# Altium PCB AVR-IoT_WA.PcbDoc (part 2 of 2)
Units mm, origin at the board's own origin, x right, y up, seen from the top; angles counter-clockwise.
Board outline 63.5 x 25.4 mm, 4 copper layers (Top-Layer, Ground Plane, Power Plane, Bottom Layer), stack 1.594 mm thick; 81 components, 91 nets, 345 pads, 206 vias.
Unrouted connection lines stored in the file: 10.
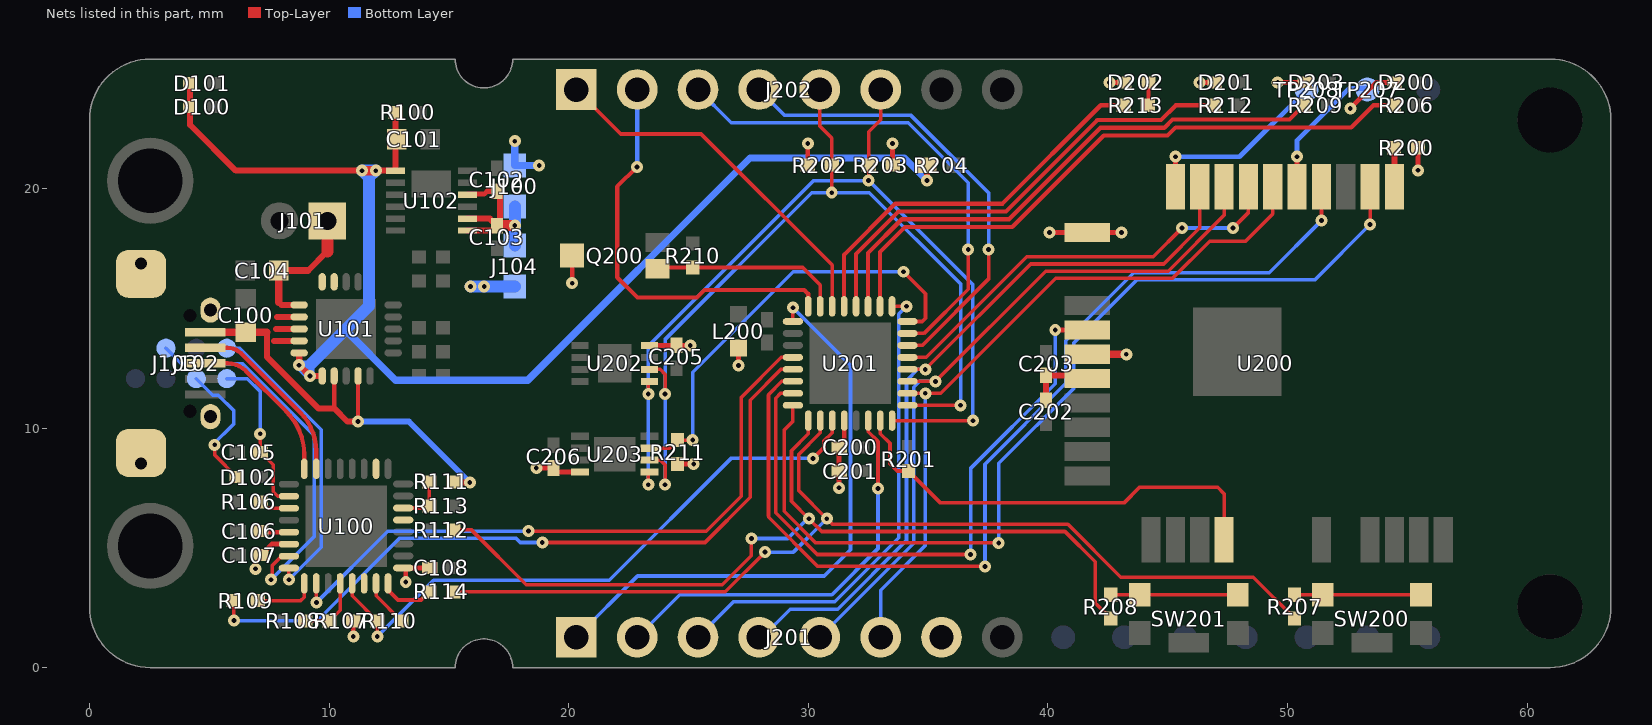
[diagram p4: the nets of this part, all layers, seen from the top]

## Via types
v1: diameter 0.5, hole 0.2, Top-Layer to Bottom Layer, 197 vias
v2: diameter 0.6, hole 0.3, Top-Layer to Bottom Layer, 9 vias

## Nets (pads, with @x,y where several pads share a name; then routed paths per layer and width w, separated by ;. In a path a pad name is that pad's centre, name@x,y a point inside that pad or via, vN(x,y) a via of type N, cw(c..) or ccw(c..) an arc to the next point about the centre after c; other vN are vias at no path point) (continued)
PA0_MBUS_RST: J201.2 U201.30 | length 17.1
  Top-Layer w0.15: U201.30@32.504,10.313 32.504,9.842 32.91,9.436 v1(32.91,7.484)
  Bottom Layer w0.15: J201.2@22.86,1.27 24.64,3.05 30.987,3.05 32.91,4.972 v1(32.91,7.484)
PA1_WINC_RST: R201.1 U200.4 U201.31 | length 18.9
  Top-Layer w0.15: U201.31@33.004,10.313 33.004,9.766 33.41,9.361 33.41,8.515 33.716,8.209 R201.1@34.185,8.209 35.519,6.875 43.177,6.875 43.827,7.525 47.086,7.525 47.356,7.255 U200.4@47.356,5.334
PA2_I2C_SDA: J202.6 R203.1 U201.32 U202.5 U203.1 | length 38.1
  Top-Layer w0.15: v1(23.323,7.639) 23.323,8.112 U203.1@23.373,8.162 ; v1(23.323,11.427) 23.323,11.9 U202.5@23.373,11.95 ; v1(32.52,20.331) R203.1@32.52,20.975 32.52,22.37 33.02,22.87 J202.6@33.02,24.13 ; U201.32@33.5,10.31 v1(36.872,10.31)
  Bottom Layer w0.15: v1(23.323,7.639) v1(23.323,11.427) 23.323,13.423 30.231,20.331 v1(32.52,20.331) 36.872,15.979 v1(36.872,10.31)
PA3_I2C_SCL: J202.5 R202.2 U201.1 U202.6 U203.2 | length 37.3
  Top-Layer w0.15: U203.2@23.373,8.662 23.825,8.662 24.023,8.464 v1(24.023,7.639) ; U202.6@23.373,12.45 23.825,12.45 24.023,12.252 v1(24.023,11.427) ; J202.5@30.48,24.13 30.48,22.605 30.98,22.105 R202.2@30.98,20.975 v1(30.98,19.825) ; U201.1@34.14,10.95 v1@36.209,10.95
  Bottom Layer w0.15: v1(24.023,7.639) v1(24.023,11.427) 24.023,13.699 30.149,19.825 v1(30.98,19.825) 32.55,19.825 36.359,16.016 v1(36.359,10.95)
PA4_SPI_MOSI: J201.6 U200.15 U201.2 | length 30.4
  Top-Layer w0.15: U201.2@34.14,11.45 v1(34.885,11.45) 35.53,11.45 40.33,16.25 45.205,16.25 46.755,17.8 48.25,17.8 49.388,18.938 U200.15@49.388,20.066
  Bottom Layer w0.15: J201.6@33.02,1.27 33.02,3.235 34.885,5.1 v1(34.885,11.45)
PA5_SPI_MISO: J201.5 U200.17 U201.3 | length 30.3
  Top-Layer w0.15: U201.3@34.14,11.95 v1(35.31,11.95) 39.91,16.55 45.025,16.55 47.356,18.881 U200.17@47.356,20.066
  Bottom Layer w0.15: J201.5@30.48,1.27 34.399,5.189 34.399,11.699 34.65,11.95 v1(35.31,11.95)
PA6_SPI_SCK: J201.4 U200.18 U201.4 | length 31.8
  Top-Layer w0.15: U201.4@34.14,12.45 v1(34.885,12.45) 39.285,16.85 44.833,16.85 46.34,18.357 U200.18@46.34,20.066
  Bottom Layer w0.15: J201.4@27.94,1.27 28.071,1.27 29.244,2.443 31.228,2.443 34.099,5.313 34.099,11.98 34.569,12.45 v1(34.885,12.45)
PA7_SPI_SS: U200.16 U201.5 | length 17.8
  Top-Layer w0.15: U201.5@34.14,12.95 34.925,12.95 39.125,17.15 44.397,17.15 v1(45.6,18.353) ; v1(47.725,18.35) 48.372,18.997 U200.16@48.372,20.066
  Bottom Layer w0.15: v1(45.6,18.353) v1@47.725,18.353
PC0_UART1_TX: J202.4 U201.6 | length 19.5
  Top-Layer w0.15: U201.6@34.14,13.45 34.751,13.45 37.525,16.224 v1(37.525,17.449)
  Bottom Layer w0.15: J202.4@27.94,24.13 29.02,23.05 34.291,23.05 37.525,19.816 v1(37.525,17.449)
PC1_UART1_RX: J202.3 U201.7 | length 20.6
  Top-Layer w0.15: U201.7@34.14,13.95 34.827,13.95 36.675,15.798 v1(36.675,17.449)
  Bottom Layer w0.15: J202.3@25.4,24.13 26.78,22.75 34.167,22.75 36.675,20.242 v1(36.675,17.449)
PC2_TEMP_INT: R211.2 U201.8 U203.3 | length 18.4
  Top-Layer w0.15: U203.3@23.373,9.162 24.21,9.162 R211.2@24.548,9.5 v1(25.175,9.5) ; v1(33.975,16.525) 34.893,15.607 34.893,14.583 34.76,14.45 U201.8@34.14,14.45
  Bottom Layer w0.15: v1(25.175,9.5) 25.175,12.326 29.374,16.525 v1(33.975,16.525)
PC3_MBUS_CS: J201.3 U201.9 | length 20.5
  Top-Layer w0.15: U201.9@33.496,15.082 34.108,15.082 v1(34.106,15.084)
  Bottom Layer w0.15: J201.3@25.4,1.27 26.88,2.75 31.111,2.75 33.781,5.42 33.781,14.76 v1(34.106,15.084)
PD0_TCA0_WO0: R206.1 U201.10 | length 26.3
  Top-Layer w0.175: U201.10@32.996,15.082 32.996,17.352 34.035,18.391 38.516,18.391 42.335,22.21 44.995,22.21 45.335,22.55 52.665,22.55 53.59,23.475 R206.1@54.45,23.475
PD1_TCA0_WO1: R209.1 U201.11 | length 23
  Top-Layer w0.175: U201.11@32.496,15.082 32.496,17.311 33.901,18.716 38.382,18.716 42.2,22.535 44.861,22.535 45.201,22.875 50.092,22.875 R209.1@50.692,23.475
PD2_TCA0_WO2: R212.1 U201.12 | length 19.7
  Top-Layer w0.175: U201.12@31.996,15.082 31.996,17.271 33.766,19.041 38.247,19.041 42.066,22.86 44.726,22.86 45.341,23.475 R212.1@46.933,23.475
PD3_TCA0_WO3: R213.1 U201.13 | length 16.4
  Top-Layer w0.175: U201.13@31.496,15.082 31.496,17.231 33.632,19.366 38.101,19.366 42.21,23.475 R213.1@43.175,23.475
PD4_TCA0_WO4: J202.1 U201.14 | length 15.4
  Top-Layer w0.15: J202.1@20.32,24.13 22.175,22.275 25.525,22.275 30.996,16.804 U201.14@30.996,15.082
PD5_LS_AIN5: Q200.2 R210.1 U201.15 | length 8
  Top-Layer w0.15: Q200.2@23.698,16.652 23.748,16.702 R210.1@25.175,16.702 29.764,16.702 30.496,15.97 U201.15@30.496,15.082
PD6_MBUS_INT: J202.2 U201.16 | length 17.2
  Top-Layer w0.175: v1(22.85,20.901) 22.025,20.076 22.025,16.295 22.871,15.449 25.349,15.449 25.67,15.77 29.83,15.77 29.996,15.604 U201.16@29.996,15.082
  Bottom Layer w0.175: v1@22.86,20.901 J202.2@22.86,24.13
PD7_MBUS_AIN7: J201.1 U201.17 | length 24.8
  Top-Layer w0.15: U201.17@29.36,14.45 v1@29.36,15.15
  Bottom Layer w0.15: J201.1@20.32,1.27 22.875,3.825 30.669,3.825 31.763,4.919 31.763,12.622 v1(29.36,15.025)
PF0_UART2_TX: U100.2 U201.20 | length 27.4
  Top-Layer w0.15: U100.2@9.462,3.52 9.462,2.709 v1(9.475,2.722) ; v1(18.32,5.7) 25.742,5.7 27.201,7.159 27.201,11.275 28.876,12.95 U201.20@29.36,12.95
  Bottom Layer w0.15: v1(9.475,2.722) 12.453,5.7 v1(18.32,5.7)
PF1_UART2_RX: R109.1 U201.21 | length 31
  Top-Layer w0.15: v1(6.025,1.963) R109.1@6.025,2.8 ; v1(18.9,5.225) 25.691,5.225 27.575,7.109 27.575,11.165 28.86,12.45 U201.21@29.36,12.45
  Bottom Layer w0.15: v1(6.025,1.963) 9.5,1.963 12.937,5.4 17.8,5.4 17.975,5.225 v1(18.9,5.225)
PF2_WINC_INT: U200.13 U201.22 | length 41.2
  Top-Layer w0.15: U201.22@29.36,11.95 28.895,11.95 28.35,11.405 28.35,11.383 28.341,11.374 28.341,6.336 28.35,6.326 28.35,6.275 30.4,4.225 v1(37.375,4.225) ; v1(51.42,18.668) U200.13@51.42,20.066
  Bottom Layer w0.15: v1(37.375,4.225) 37.375,8.492 40.75,11.867 40.75,13.649 43.585,16.484 49.236,16.484 v1(51.42,18.668)
PF3_WINC_EN: U200.22 U201.23 | length 26.6
  Top-Layer w0.15: U201.23@29.36,11.45 28.841,11.45 28.641,11.25 28.641,6.46 30.376,4.725 v1(36.775,4.725)
  Top-Layer w0.2: v1(40.309,14.097) U200.22@41.641,14.097
  Bottom Layer w0.15: v1(36.775,4.725) 36.775,8.316 40.309,11.85 v1(40.309,14.097)
PF4_WINC_WAKE: U200.11 U201.24 | length 39.7
  Top-Layer w0.15: U201.24@29.36,10.95 29.36,10.283 29,9.923 29,6.525 30.318,5.207 v1(37.95,5.207) ; v1(53.452,18.502) U200.11@53.452,20.066
  Bottom Layer w0.15: v1(37.95,5.207) 37.95,8.528 41.075,11.653 41.075,13.55 43.709,16.184 51.134,16.184 v1(53.452,18.502)
PF5_SW1_DGI: R112.2 R208.1 U201.25 | length 37.4
  Top-Layer w0.15: R112.2@15.175,5.75 15.945,5.75 18.231,3.464 26.415,3.464 27.625,4.674 v1(27.625,5.391) ; U201.25@30.004,10.313 30.004,9.761 29.3,9.057 29.3,6.945 v1(30.025,6.22) 30.563,5.682 40.713,5.682 41.975,4.42 41.975,2.699 R208.1@42.624,2.05
  Bottom Layer w0.15: v1(27.625,5.391) 29.15,5.391 v1@30.025,6.266
PF6_SW0_DGI: R114.2 R207.1 U201.26 | length 43.1
  Top-Layer w0.15: R114.2@15.175,3.164 26.539,3.164 v1(28.2,4.825) ; U201.26@30.504,10.313 30.504,9.801 29.6,8.897 29.6,7.395 v1(30.775,6.22) 31.013,5.982 40.838,5.982 43.045,3.775 48.575,3.775 R207.1@50.3,2.05
  Bottom Layer w0.15: v1(28.2,4.825) 29.38,4.825 v1(30.775,6.22)
REG_ENABLE: U100.13
RESERVED: U100.6
S0_2_TX: R110.2 U100.7 | length 2
  Top-Layer w0.15: U100.7@11.962,3.52 11.962,3 R110.2@13.012,1.95
S0_3_CLK: R114.1 U100.8 | length 2.3
  Top-Layer w0.15: U100.8@12.462,3.52 12.462,3.24 12.877,2.825 13.836,2.825 R114.1@14.175,3.164
S1_0_TX: R109.2 U100.1 | length 2.6
  Top-Layer w0.15: R109.2@7.025,2.8 8.823,2.8 8.962,2.939 U100.1@8.962,3.52
S\R\S\T\: C105.2 J102.6 U100.26 | length 6.8
  Top-Layer w0.15: C105.2@7.125,8.995 v1(7.125,9.763) ; C105.2@7.147,8.995 7.675,8.467 7.675,7.342 7.861,7.156 U100.26@8.325,7.156
  Bottom Layer w0.15: J102.6@5.73,12.065 6.59,12.065 7.125,11.53 v1(7.125,9.763)
SHIELD: J103.6 J103.7 J103.8 J103.9
STATUS_LED: R106.2 U100.27 | length 1.3
  Top-Layer w0.15: R106.2@7.172,6.92 7.435,6.656 U100.27@8.325,6.656
SW0: R207.2 SW200.2 SW200.4 | length 5.3
  Top-Layer w0.15: R207.2@50.3,3.043 SW200.4@51.475,3.043 SW200.2@55.575,3.043
SW1: R208.2 SW201.2 SW201.4 | length 5.3
  Top-Layer w0.15: R208.2@42.624,3.05 43.82,3.05 SW201.4@43.827,3.043 SW201.2@47.927,3.043 SW201.2@47.925,3.045
SWCLK: J102.1 U100.31 | length 15.9
  Top-Layer w0.15: v1(7.575,3.673) 7.625,3.723 7.625,4.264 8.017,4.656 U100.31@8.325,4.656
  Bottom Layer w0.15: J102.1@3.19,13.335 3.835,12.69 6.39,12.69 9.372,9.707 9.372,5.471 v1(7.575,3.673)
SWDIO: J102.5 U100.32 | length 12.7
  Top-Layer w0.15: v1(8.322,3.673) U100.32@8.322,4.16
  Bottom Layer w0.15: J102.5@5.73,13.335 6.262,13.335 9.672,9.925 9.672,5.024 v1(8.322,3.673)
UPDI: R110.1 U100.5 U201.27 | length 25.8
  Top-Layer w0.15: U100.5@10.962,3.52 10.962,3 R110.1@12.012,1.95 v1(12.012,1.302) ; v1(30.2,8.734) 30.656,9.19 30.656,9.461 31.004,9.81 U201.27@31.004,10.313
  Bottom Layer w0.15: v1(12.012,1.302) 14.36,3.65 21.691,3.65 26.775,8.734 v1(30.2,8.734)
USBD_N: J103.2 U100.23 | length 7.6
  Top-Layer w0.18: J103.2@4.83,13.35 5.77,13.35 cw(c5.77,12.555) 6.332,13.117 8.787,10.663 cw(c7.157,9.032) 9.462,9.032 U100.23@9.462,8.3
USBD_P: J103.3 U100.24 | length 6.8
  Top-Layer w0.18: J103.3@4.83,12.7 5.77,12.7 cw(c5.77,11.633) 6.524,12.388 8.218,10.694 cw(c6.422,8.898) 8.962,8.898 U100.24@8.962,8.3
VBUS: C100.1 J103.1 R111.2 U101.2 U101.4 U101.17 U101.18 U101.19 | length 21.1
  Top-Layer w0.175: 10.212,10.825 U101.2@10.212,12.174 ; v1(11.212,10.275) U101.4@11.212,12.174
  Top-Layer w0.25: 7.4,14 7.4,12.976 9.551,10.825 10.212,10.825 10.762,10.275 v1(11.212,10.275) ; 7.694,13.639 U101.19@8.747,13.639 ; 7.778,14.139 U101.18@8.747,14.139 ; 7.817,14.639 U101.17@8.747,14.639 ; R111.2@15.175,7.73 v1(15.875,7.73)
  Top-Layer w0.325: J103.1@4.83,14 6.626,14 7.4,14
  Bottom Layer w0.25: v1(11.212,10.275) 13.33,10.275 v1(15.875,7.73)
VBUS_ADC: R111.1 R113.1 U100.14 | length 2.1
  Top-Layer w0.15: U100.14@13.094,6.664 14.099,6.664 14.175,6.74 R111.1@14.175,7.73
VCC_BAT: C104.2 J101.1 U101.14 U101.15 U101.16 | length 5.4
  Top-Layer w0.25: 7.9,15.253 8.014,15.139 U101.16@8.747,15.139 ; 9.125,16.575 9.925,17.375
  Top-Layer w0.3: 7.9,15.253 C104.2@7.9,16.575 ; C104.2@8,16.575 9.125,16.575
  Top-Layer w0.5: 9.925,17.375 J101.1@9.925,18.35
VCC_DEBUGGER: C107.2 C108.1 D102.2 J102.4 J104.1 R107.2 U100.9 U100.30 | length 12.1
  Top-Layer w0.15: v1(5.225,9.3) 5.225,8.875 D102.2@6.15,7.95
  Top-Layer w0.2: v1@6.925,4.075 v1(6.925,4.125) 6.925,4.476 C107.2@7.147,4.698 7.605,5.156 U100.30@8.325,5.156 ; v1(11.012,1.302) R107.2@11.012,1.95 R107.2@11.012,2.025 ; v1(13.2,3.572) 13.2,4.058 U100.9@13.094,4.164 C108.1@14.2,4.164
  Bottom Layer w0.15: J102.4@4.46,12.065 5.15,11.375 5.375,11.375 6.016,10.734 6.016,10.172 5.15,9.306 v1@5.15,9.25
  Bottom Layer w0.5: v1(15.901,15.913) v1(16.475,15.913) J104.1@17.75,15.913
VCC_MCU_CORE: C106.2 U100.29 | length 1.2
  Top-Layer w0.2: C106.2@7.147,5.7 7.191,5.656 U100.29@8.325,5.656
VCC_MUX: C101.1 D100.2 D101.2 R100.1 R204.2 U101.1 U101.20 U102.1 | length 57.1
  Top-Layer w0.25: D101.2@4.2,24.425 D100.2@4.2,23.402 4.2,22.65 6.109,20.741 v1(11.375,20.741) ; v1(11.95,20.741) U102.1@12.773,20.741 12.773,21.997 C101.1@12.826,22.05 12.775,22.101 R100.1@12.775,23.175 ; v1(34.96,20.335) R204.2@34.96,20.975
  Top-Layer w0.27: U101.20@8.747,13.139 v1(8.747,12.625) 8.749,12.625 v1(9.2,12.172) U101.1@9.712,12.174
  Top-Layer w0.4: v1(11.375,20.741) v1(11.95,20.741)
  Bottom Layer w0.3: 10.674,14.1 12.776,11.998 18.29,11.998 27.57,21.278 34.017,21.278 v1(34.96,20.335)
  Bottom Layer w0.4: v1(8.747,12.625) 9.198,12.626 ; v1(8.747,12.625) 9.199,12.173 9.199,12.625
  Bottom Layer w0.5: 9.199,12.625 10.674,14.1 11.661,15.087 ; v1(11.375,20.741) v1@11.384,20.741 ; v1@11.375,20.75 v1@11.384,20.741 ; 11.662,15.087 11.662,20.462 ; v1@11.946,20.746 v1@11.941,20.741 ; v1(11.95,20.741) v1@11.941,20.741 ; v1@11.384,20.741 11.662,20.462 ; v1@11.384,20.741 v1@11.941,20.741 ; 11.663,20.462 v1@11.941,20.741
VCC_P1V3: C202.2 C203.1 U200.24 | length 2.8
  Top-Layer w0.25: C202.2@39.923,11.156 C203.1@39.923,12.2 41.506,12.2 U200.24@41.641,12.065
VCC_P3V3: C102.1 C103.2 J100.2 J104.2 U102.7 U102.8 U102.10 | length 7.9
  Top-Layer w0.2: U102.10@15.773,19.741 15.798,19.766 16.475,19.766 16.6,19.891
  Top-Layer w0.225: 16.6,19.891 C102.1@16.998,19.891 C102.1@17.125,19.764 ; C103.2@16.795,18.241 C103.2@17.004,18.45 C103.2@17.125,18.571
  Top-Layer w0.25: U102.7@15.773,18.241 C103.2@16.795,18.241 ; U102.8@15.773,18.741 16.712,18.741 C103.2@16.998,18.455 ; C103.2@17.125,18.571 C102.1@17.125,19.764
  Top-Layer w0.45: C103.2@17.004,18.45 v1(17.75,18.45)
  Bottom Layer w0.5: J104.2@17.75,17.613 v1(17.75,18.45) J100.2@17.75,19.254
VCC_TARGET: C200.1 C201.1 C205.2 C206.1 D200.2 D201.2 D202.2 D203.2 J100.1 J201.7 L200.2 Q200.1 R200.2 R202.1 R203.2 R211.1 U200.20 U200.23 U201.28 U202.8 U203.8 | length 23.2
  Top-Layer w0.2: v1(18.65,8.333) C206.1@19.375,8.333 19.546,8.162 U203.8@20.473,8.162 ; v1(20.148,16.048) Q200.1@20.148,17.202 ; U202.8@23.373,13.45 C205.2@24.498,13.45 v1(25.075,13.45) ; R211.1@24.548,8.5 v1(25.216,8.5) ; v1(27.085,12.615) L200.2@27.085,13.348 ; R202.1@29.98,20.975 v1(29.98,21.878) ; C200.1@31.26,9.209 31.504,9.453 U201.28@31.504,10.313 ; C201.1@31.281,8.209 C201.1@31.288,8.203 ; v1(31.288,7.506) C201.1@31.288,8.203 ; C200.1@31.288,9.198 C201.1@31.288,8.203 ; R203.2@33.52,20.975 v1(33.52,21.878) ; v1(40.073,18.161) U200.20@41.641,18.161 v1(43.08,18.161) ; v1(42.575,24.425) D202.2@43.225,24.425 ; v1(46.333,24.425) D201.2@46.983,24.425 ; v1(49.592,24.425) D203.2@50.717,24.425 D203.2@50.742,24.425 ; v1(52.625,23.341) 53.709,24.425 D200.2@54.475,24.425 ; v1(55.45,20.759) R200.2@55.45,21.7
  Top-Layer w0.3: U200.23@41.641,13.081 v1@43.272,13.081
  Bottom Layer w0.3: v1(17.75,21.975) J100.1@17.75,20.954 v1(18.771,20.954)
  other v1: 43.275,13.078
VTG_ADC: R107.1 R108.2 U100.4 | length 2.8
  Top-Layer w0.15: R108.2@9.012,1.95 R107.1@10.012,1.95 10.462,2.4 U100.4@10.462,3.52
VTG_EN: U100.18
WIFI: D202.1 R213.2 | length 1
  Top-Layer w0.175: R213.2@44.175,23.475 44.2,23.5 D202.1@44.2,24.425
WINC_SPI_CFG: R200.1 U200.10 | length 1.6
  Top-Layer w0.25: U200.10@54.468,20.066 R200.1@54.468,21.7
WINC_UART_RX: TP208.1 U200.19 | length 7.9
  Top-Layer w0.2: U200.19@45.324,20.066 v1(45.324,21.329)
  Bottom Layer w0.2: v1(45.324,21.329) 47.999,21.329 TP208.1@50.8,24.13 ; TP208.1@50.78,24.15 TP208.1@50.8,24.17
WINC_UART_TX: TP207.1 U200.14 | length 5.8
  Top-Layer w0.2: U200.14@50.404,20.066 v1(50.404,21.329)
  Bottom Layer w0.2: v1(50.404,21.329) 50.404,22.018 52.556,24.17 TP207.1@53.34,24.17
pads on no net: J101.0 J102.3 J103.0 J103.4 J103.10 J103.11 J201.0 J202.0 Q200.3 U101.6 U200.5 U200.6 U200.7 U200.8 U202.1 U202.2 U202.3 U202.7 U203.0

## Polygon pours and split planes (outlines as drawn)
GND on Bottom Layer "Bottom Layer-GND" (solid, remove dead copper, pour order 14): 57.236,25.4 57.236,0 0,0 0,25.4
VCC_MUX on Top-Layer "Top-Layer-VCC_MUX" (solid, remove dead copper, pour order 10): 7.639,13.639 9.85,13.639 9.85,11.25 8.97,11.25 7.639,12.611
VBUS on Top-Layer "Top-Layer-VBUS" (solid, pour order 2): 9.135,14.8 6.1,14.8 6.116,13.475 9.135,13.475
VCC_BAT on Top-Layer "Top-Layer-VCC_BAT" (solid, pour order 4): 9.15,19.425 9.15,17.75 8.6,17.2 7.5,17.2 7.5,14.95 9.775,14.95 10.475,15.65 10.475,19.425
GND on Top-Layer "Top Layer-GND" (solid, remove dead copper, pour order 16): 57.236,25.4 57.236,0 0,0 0,25.4
no net on Top Overlay (solid): 23.968,8.552 25.943,11.277 ccw(c25.346,11.684) 25.968,12.052 24.393,14.502 22.242,11.494 cw(c28.567,13.292) 22.17,14.812 cw(c29.161,13.199) 24.618,18.752 cw(c30.212,11.154) 27.004,20.027 cw(c29.594,12.818) 32.568,19.877 37.093,12.702 37.092,12.702 cw(c28.92,13.715) 36.712,11.054 32.793,17.177 ccw(c31.693,16.502) 32.368,17.602 ccw(c32.13,17.139) 32.043,17.652 ccw(c32.393,16.577) 31.468,17.227 30.168,15.402 34.743,8.177 cw(c29.377,14.584) 29.318,6.227 cw(c29.662,14.337)
GND on Ground Plane (split plane): 2.54,24.89 14.829,24.89 14.88,24.746 14.952,24.594 15.038,24.45 15.138,24.315 15.251,24.191 15.375,24.078 15.51,23.978 15.654,23.892 15.806,23.82 15.964,23.764 16.126,23.723 16.292,23.698 16.46,23.69 16.628,23.698 16.794,23.723 16.956,23.764 17.114,23.82 17.266,23.892 17.41,23.978 17.545,24.078 17.669,24.191 17.782,24.315 17.882,24.45 17.968,24.594 18.04,24.746 18.091,24.89 57.225,24.89 57.225,0.51 18.091,0.51 18.04,0.654 17.968,0.806 17.882,0.95 17.782,1.085 17.669,1.209 17.545,1.322 17.41,1.422 17.266,1.508 17.114,1.58 16.956,1.636 16.794,1.677 16.628,1.702 16.46,1.71 16.292,1.702 16.126,1.677 15.964,1.636 15.806,1.58 15.654,1.508 15.51,1.422 15.375,1.322 15.251,1.209 15.138,1.085 15.038,0.95 14.952,0.806 14.88,0.654 14.829,0.51 2.54,0.51 2.524,0.509 2.341,0.518 2.144,0.547 1.95,0.596 1.762,0.663 1.582,0.748 1.411,0.851 1.251,0.969 1.103,1.103 0.969,1.251 0.851,1.411 0.748,1.582 0.663,1.762 0.596,1.95 0.547,2.144 0.518,2.341 0.509,2.524 0.51,2.54 0.51,22.86 0.509,22.876 0.518,23.059 0.547,23.256 0.596,23.45 0.663,23.638 0.748,23.818 0.851,23.989 0.969,24.149 1.103,24.297 1.251,24.431 1.411,24.549 1.582,24.652 1.762,24.737 1.95,24.804 2.144,24.853 2.341,24.882 2.524,24.891
VCC_TARGET on Power Plane (split plane): 2.54,24.89 14.829,24.89 14.88,24.746 14.952,24.594 15.038,24.45 15.138,24.315 15.251,24.191 15.375,24.078 15.51,23.978 15.654,23.892 15.806,23.82 15.964,23.764 16.126,23.723 16.292,23.698 16.46,23.69 16.628,23.698 16.794,23.723 16.956,23.764 17.114,23.82 17.266,23.892 17.41,23.978 17.545,24.078 17.669,24.191 17.782,24.315 17.882,24.45 17.968,24.594 18.04,24.746 18.091,24.89 57.225,24.89 57.225,0.51 18.091,0.51 18.076,0.553 18.076,16.2 18.071,16.239 18.056,16.276 18.032,16.307 16.782,17.557 16.751,17.581 16.736,17.587 16.714,17.596 16.675,17.601 0.51,17.601 0.51,22.86 0.509,22.876 0.518,23.059 0.547,23.256 0.596,23.45 0.663,23.638 0.748,23.818 0.851,23.989 0.969,24.149 1.103,24.297 1.251,24.431 1.411,24.549 1.582,24.652 1.762,24.737 1.95,24.804 2.144,24.853 2.341,24.882 2.524,24.891
VCC_DEBUGGER on Power Plane (split plane): 17.774,16.137 17.774,1.094 17.669,1.209 17.545,1.322 17.41,1.422 17.266,1.508 17.114,1.58 16.956,1.636 16.794,1.677 16.628,1.702 16.46,1.71 16.292,1.702 16.126,1.677 15.964,1.636 15.806,1.58 15.654,1.508 15.51,1.422 15.375,1.322 15.251,1.209 15.138,1.085 15.038,0.95 14.952,0.806 14.88,0.654 14.829,0.51 2.54,0.51 2.524,0.509 2.341,0.518 2.144,0.547 1.95,0.596 1.762,0.663 1.582,0.748 1.411,0.851 1.251,0.969 1.103,1.103 0.969,1.251 0.851,1.411 0.748,1.582 0.663,1.762 0.596,1.95 0.547,2.144 0.518,2.341 0.509,2.524 0.51,2.54 0.51,17.299 16.612,17.299

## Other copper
Top-Layer:
  pour cut-out: 30.763,7.753
  pour cut-out: 13.398,19.541 13.398,17.987 15.098,17.987 15.098,19.541
Bottom Layer:
  region net NetTP200_1: 55.381,1.27 56.379,1.27 56.379,0.255 55.381,0.255
  region net NetTP201_1: 52.841,1.27 53.839,1.27 53.839,0.255 52.841,0.255
  region net NetTP202_1: 50.301,1.27 51.299,1.27 51.299,0.255 50.301,0.255
  region net NetTP206_1: 47.761,1.27 48.759,1.27 48.759,0.255 47.761,0.255
  region net NetTP205_1: 45.221,1.27 46.219,1.27 46.219,0.255 45.221,0.255
  region net NetTP204_1: 42.681,1.27 43.679,1.27 43.679,0.255 42.681,0.255
  region net NetTP203_1: 40.141,1.27 41.139,1.27 41.139,0.255 40.141,0.255
  region net GND: 56.379,24.13 55.381,24.13 55.381,25.145 56.379,25.145
  region net WINC_UART_RX: 51.299,24.13 50.301,24.13 50.301,25.145 51.299,25.145
  region net WINC_UART_TX: 53.839,24.13 52.841,24.13 52.841,25.145 53.839,25.145
Ground Plane (plane layer: these items are gaps in the copper):
  pour cut-out: 57.225,25.4 57.225,0 63.5,0 63.5,25.4
Power Plane (plane layer: these items are gaps in the copper):
  pour cut-out: 57.225,25.4 57.225,0 63.5,0 63.5,25.4
  lines w0.3: -0.35,17.45 16.675,17.45 17.925,16.2 17.925,0 ; 40.425,0.075 42.85,0.075

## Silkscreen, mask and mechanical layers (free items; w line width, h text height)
Top Overlay:
  pour cut-out: 25.068,15.452 26.343,17.227 cw(c27.162,16.771) 27.004,17.695 cw(c26.873,16.744) 27.718,17.202 31.568,11.152 30.193,9.202 cw(c29.42,9.7) 29.594,8.797 cw(c29.543,9.147) 29.393,8.827 cw(c29.964,9.793) 28.943,9.327
  pour cut-out: 24.072,10 24.072,8 25.023,8 25.023,10
  pour cut-out: 35.211,16.425 36.3,16.425 36.3,9.025 35.162,9.025
  pour cut-out: 20.012,13.802 23.923,13.802 23.923,11.6 19.988,11.6
  pour cut-out: 19.4,18.374 19.4,16.048 24.45,16.048 24.45,18.349
  pour cut-out: 33.71,7.709 33.71,9.709 34.66,9.709 34.66,7.709
  pour cut-out: 30.763,7.753 32.763,7.753 32.763,8.653 30.763,8.653
  pour cut-out: 30.763,8.748 32.763,8.748 32.763,9.648 30.763,9.648
  pour cut-out: 24.7,18.202 24.7,16.202 25.65,16.202 25.65,18.202
  pour cut-out: 24.048,13.975 24.048,11.975 24.948,11.975 24.948,13.975
  pour cut-out: 26.535,15.298 26.535,12.798 27.635,12.798 27.635,15.298
  pour cut-out: 27.835,15.048 27.835,13.047 28.735,13.047 28.735,15.048
  pour cut-out: 34.7,14.946 34.7,10.45 34.25,10.45 34.25,10.196 34,10.196 34,9.75 28.8,9.75 28.8,14.948 29.25,14.946 29.25,15.196 29.5,15.196 29.5,15.65 34,15.65 34,15.196 34.25,15.196 34.25,14.946
  lines w0.15: 21.59,0.425 21.59,3.7 ; 21.59,21.7 21.59,24.975 ; 24.13,0.425 24.13,3.7 ; 24.13,21.7 24.13,24.975 ; 26.67,0.425 26.67,3.7 ; 26.67,21.7 26.67,24.975 ; 29.21,21.7 29.21,24.975 ; 29.31,0.425 29.31,3.7 ; 31.75,0.425 31.75,3.7 ; 31.75,21.7 31.75,24.975 ; 34.29,0.425 34.29,3.7 ; 34.29,21.7 34.29,24.975 ; 36.83,0.425 36.83,3.7 ; 36.83,21.7 36.83,24.975
  lines w0.2: 5.9,10.265 16.46,10.265 ; 16.46,1.3 16.46,24.1
  lines w0.305: 21.59,0 21.59,2.54 ; 21.59,22.86 21.59,25.4 ; 41.91,22.86 39.37,25.4 ; 39.37,25.4 19.05,25.4 19.05,22.86 39.37,22.86 39.37,25.4 ; 19.05,0 39.37,0 39.37,2.54 19.05,2.54 19.05,0
  text "WIFI" at 45.9,22.6 h0.75 r90
  text "GND" at 2.9,22.425 h0.9 r90
  text "CONN" at 49.658,22.225 h0.75 r90
  text "DATA" at 53.4,22.225 h0.75 r90
  text "PWM" at 19.32,21.775 h0.75
  text "INT" at 21.923,21.775 h0.75
  text "RX" at 24.775,21.775 h0.75
  text "TX" at 27.315,21.775 h0.75
  text "SCL" at 29.48,21.775 h0.75
  text "SDA" at 32.02,21.775 h0.75
  text "5V" at 34.935,21.775 h0.75
  text "GND" at 37.1,21.775 h0.75
  text "ERROR" at 57.175,21.475 h0.75 r90
  text "WINC1510" at 57.75,20.475 h0.75
  text "+" at 11.725,18.325 h0.9 r90
  text "-" at 6.275,18.2 h0.9
  text "®" at 34.243,18.154 h2.54
  text "CHGSTAT" at 5.55,17.845 h0.75 r90
  text "LIPO" at 9.437,16.775 h0.75
  text "LIGHT" at 18.825,15.513 h0.75 r90
  text "CHARGER" at 7.75,10.65 h0.9
  text "ECC608" at 18.825,10.588 h0.75 r90
  text "ATMEGA4808" at 36.125,9.1 h0.75 r90
  text "PS" at 4.175,7.6 h0.75
  text "TEMP" at 18.825,7.216 h0.75 r90
  text "SECURE SMART CONNECTED" at 19.688,4.25 h0.9
  text "AN" at 19.695,2.85 h0.75
  text "RST" at 21.86,2.85 h0.75
  text "CS" at 24.775,2.85 h0.75
  text "SCK" at 26.94,2.85 h0.75
  text "SDO" at 29.48,2.85 h0.75
  text "SDI" at 32.145,2.85 h0.75
  text "3V3" at 34.56,2.85 h0.75
  text "GND" at 37.1,2.85 h0.75
  text "SW1" at 49.5,1.001 h0.75 r90
  text "SW0" at 57.075,1.001 h0.75 r90
  text "GND" at 2.915,0.555 h0.9 r90
  text "DEBUGGER" at 7.15,0.275 h0.9
Bottom Overlay:
  lines w0.15: 40.063,4.45 63.063,4.45 63.063,20.95 40.063,20.95 40.063,4.45
  lines w0.305: 21.59,0 21.59,2.54 ; 21.59,22.86 21.59,25.4 ; 41.91,22.86 39.37,25.4 ; 39.37,25.4 19.05,25.4 19.05,22.86 39.37,22.86 39.37,25.4 ; 19.05,0 39.37,0 39.37,2.54 19.05,2.54 19.05,0
  text "GND" at 2.915,24.845 h0.9 r90
  text "LIPO / BATT" at 10.35,24.324 h0.9 r90
  text "RX" at 51.175,23.325 h0.75 r90
  text "TX" at 53.715,23.325 h0.75 r90
  text "GND" at 56.255,23.325 h0.75 r90
  text "TARGET" at 16.7,23 h0.75 r90
  text "PD4 / PWM" at 20.784,22.35 h1.5 r90
  text "PD6 / INT" at 23.324,22.35 h1.5 r90
  text "PC1 / RX" at 25.864,22.35 h1.5 r90
  text "PC0 / TX" at 28.404,22.35 h1.5 r90
  text "PA3 / SCL" at 30.944,22.35 h1.5 r90
  text "PA2 / SDA" at 33.484,22.35 h1.5 r90
  text "+5V" at 36.024,22.35 h1.5 r90
  text "GND" at 38.564,22.35 h1.5 r90
  text "Microchip © 2019" at 43.261,20.251 h2 r90
  text "VCC" at 15.45,19.4 h0.75 r90
  text "b" at 71.75,19.217 h22 r90
  text "A08-2937 Rev5" at 44.768,18.958 h2 r90
  text "E" at 39.665,18.675 h5.8 r90
  text "nEDBG" at 16.7,18.03 h0.75 r90
  text "-" at 6.825,17.9 h1.5
  text "+" at 12.025,17.875 h1.5
  text "c" at 11.475,16.35 h6.8 r90
  text "BOOT" at 1.275,13.375 h0.75 r90
  text "C" at 35.575,11.458 h4.45
  text "-IoT" at 27.175,11.386 h5
  text "MOSI / PA4" at 33.484,9.79 h1.5 r90
  text "MISO / PA5" at 30.944,9.765 h1.5 r90
  text "SCK / PA6" at 28.404,9.199 h1.5 r90
  text "RST / PA0" at 23.324,8.976 h1.5 r90
  text "R" at 12.434,8.8 h4 r90
  text "AN / PD7" at 20.784,8.409 h1.5 r90
  text "CS / PC3" at 25.864,8.259 h1.5 r90
  text "t" at 16.92,6.515 h4.57 r90
  text "+3.3V" at 36.024,6.453 h1.5 r90
  text "GND" at 38.564,5.795 h1.5 r90
  text "GP1" at 41.005,4.11 h0.75 r90
  text "GP3" at 43.545,4.11 h0.75 r90
  text "GP4" at 46.085,4.11 h0.75 r90
  text "GP5" at 48.625,4.11 h0.75 r90
  text "GP6" at 51.165,4.11 h0.75 r90
  text "SCL" at 53.705,4.11 h0.75 r90
  text "SDA" at 56.245,4.11 h0.75 r90
  text "GND" at 2.915,2.955 h0.9 r90
Board (M1):
  the board outline again, w0.1
Conn. Pos. (M4):
  circle w0.4: c60.96,22.86 r1.6
  circle w0.4: c60.96,2.54 r1.6
  circle w0.35: c20.32,1.27 r0.65
  circle w0.35: c22.86,1.27 r0.65
  circle w0.35: c25.4,1.27 r0.65
  circle w0.35: c27.94,1.27 r0.65
  circle w0.35: c30.48,1.27 r0.65
  circle w0.35: c33.02,1.27 r0.65
  circle w0.35: c38.1,1.27 r0.65
  circle w0.35: c35.56,1.27 r0.65
  circle w0.35: c20.32,24.13 r0.65
  circle w0.35: c22.86,24.13 r0.65
  circle w0.35: c25.4,24.13 r0.65
  circle w0.35: c27.94,24.13 r0.65
  circle w0.35: c30.48,24.13 r0.65
  circle w0.35: c33.02,24.13 r0.65
  circle w0.35: c38.1,24.13 r0.65
  circle w0.35: c35.56,24.13 r0.65
  circle w0.4: c2.54,5.08 r1.6
  circle w0.4: c2.54,20.32 r1.6
  region: 1.1,17.424 1.1,15.45 3.2,15.45 3.2,17.424
  region: 3.2,7.975 3.2,9.95 1.125,9.95 1.125,7.975
  region: 5.68,13.825 5.68,14.175 3.98,14.175 3.98,13.825
  region: 5.68,13.175 5.68,13.525 3.98,13.525 3.98,13.175
  region: 5.68,12.525 5.68,12.875 3.98,12.875 3.98,12.525
  region: 5.68,11.875 5.68,12.225 3.98,12.225 3.98,11.875
  region: 5.68,11.225 5.68,11.575 3.98,11.575 3.98,11.225
  text "Connector Placement" at 12.65,28.965 h5
TP Pos. (M5):
  circle w0.5: c3.19,13.335 r0.25
  circle w0.5: c3.19,12.065 r0.25
  circle w0.5: c4.46,12.065 r0.25
  circle w0.5: c4.46,13.335 r0.25
  circle w0.5: c5.73,13.335 r0.25
  circle w0.5: c5.73,12.065 r0.25
  circle w0.4: c2.54,5.08 r1.6
  circle w0.4: c2.54,20.32 r1.6
  lines w0.1: 2.79,10.66 3.19,11.06 ; 2.79,14.74 3.19,14.34 ; 3.59,10.66 3.19,11.06 ; 3.59,14.74 3.19,14.34 ; 4.06,10.66 4.46,11.06 ; 4.86,10.66 4.46,11.06 ; 5.33,10.66 5.73,11.06 ; 5.33,14.74 5.73,14.34 ; 6.13,10.66 5.73,11.06 ; 6.13,14.74 5.73,14.34 ; 12.18,6.61 3.19,6.61 3.19,11.06 ; 12.18,8.36 4.46,8.36 4.46,11.06 ; 12.18,10.11 5.73,10.11 5.73,11.06 ; 12.18,15.29 5.73,15.29 5.73,14.34 ; 12.18,17.04 3.19,17.04 3.19,14.34
  text "Test Point Placement" at 13.075,28.965 h5
  text "J101-1_SWCLK" at 12.88,16.623 h1
  text "J101-5_SWD" at 12.88,14.873 h1
  text "J101-6_RST" at 12.88,9.443 h1
  text "J101-4_VCC" at 12.88,7.693 h1
  text "J101-2_GND" at 12.88,5.943 h1
  text "2x5 50mil test-point pattern" at 7.15,0.515 h1
Test Jig (M9):
  circle w0.5: c-43.81,-2.935 r1.25
  circle w0.5: c-43.81,28.315 r1.25
  circle w0.5: c2.54,5.08 r1.5
  circle w0.5: c2.54,20.32 r1.5
  lines w0.5: -38.31,-9.685 -38.31,35.065 cw(c-36.81,35.065) -35.31,35.065 -6.31,35.065 cw(c-4.81,35.065) -3.31,35.065 -3.31,-9.685 ; -38.309,-9.685 ccw(c-36.809,-9.685) -35.309,-9.685 -6.309,-9.685 ccw(c-4.809,-9.685) -3.309,-9.685 ; -49.31,-17.685 -46.31,-20.685 86.47,-20.685 89.47,-17.686 89.47,43.04 86.47,46.04 -46.31,46.04 -49.31,43.04 -49.31,-17.685 ; 0.69,10.39 ccw(c2.19,10.39) 2.19,8.89 5.04,8.89 cw(c5.04,7.39) 6.54,7.39 6.54,6.58 ccw(c8.04,6.58) 8.04,5.08 59.19,5.08 ccw(c59.19,6.58) 60.69,6.58 60.69,18.82 ccw(c59.19,18.82) 59.19,20.32 8.04,20.32 ccw(c8.04,18.82) 6.54,18.82 6.54,18.01 cw(c5.04,18.01) 5.04,16.51 2.19,16.51 ccw(c2.19,15.01) 0.69,15.01 0.69,10.39
  text "Xplained Nano FCT" at -29.74,38.649 h10
Test Jig Pin (M10):
  circle w0.1: c76.2,5.08 r2.85
  circle w0.1: c76.2,20.32 r2.85
  circle w0.5: c2.54,20.32 r2
  circle w0.5: c2.54,20.32 r1.25
  circle w0.5: c2.54,5.08 r1.25
  circle w0.5: c2.54,5.08 r2
  circle w0.1: c2.54,20.32 r2.85
  circle w0.1: c2.54,5.08 r2.85

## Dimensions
15.26,25.4 to 16.46,24.2 on Dimentions (M6)
16.46,24.1 to 0,22.86 on Dimentions (M6)
62.56,2.54 to 60.96,0 on Conn. Pos. (M4)
2.54,0 to 2.54,5.08 on Conn. Pos. (M4)
5.98,12.065 to 5.98,13.335 on TP Pos. (M5)
62.56,2.54 to 62.56,22.86 on Conn. Pos. (M4)
20.32,24.78 to 2.54,21.92 on Conn. Pos. (M4)
22.86,0.62 to 20.32,0.62 on Conn. Pos. (M4)
2.54,5.08 to 1.9,12.7 on Conn. Pos. (M4)
60.96,25.4 to 60.96,0 on Dimentions (M6)
63.5,2.54 to 0,2.54 on Dimentions (M6)
2.54,3.48 to 60.96,0.94 on Conn. Pos. (M4)
2.54,25.4 to 0.94,20.32 on Conn. Pos. (M4)
0,22.86 to 2.54,21.92 on Conn. Pos. (M4)
3.19,11.815 to 2.54,3.48 on TP Pos. (M5)
2.94,12.065 to 0.94,5.08 on TP Pos. (M5)
2.94,13.335 to 0.94,5.08 on TP Pos. (M5)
